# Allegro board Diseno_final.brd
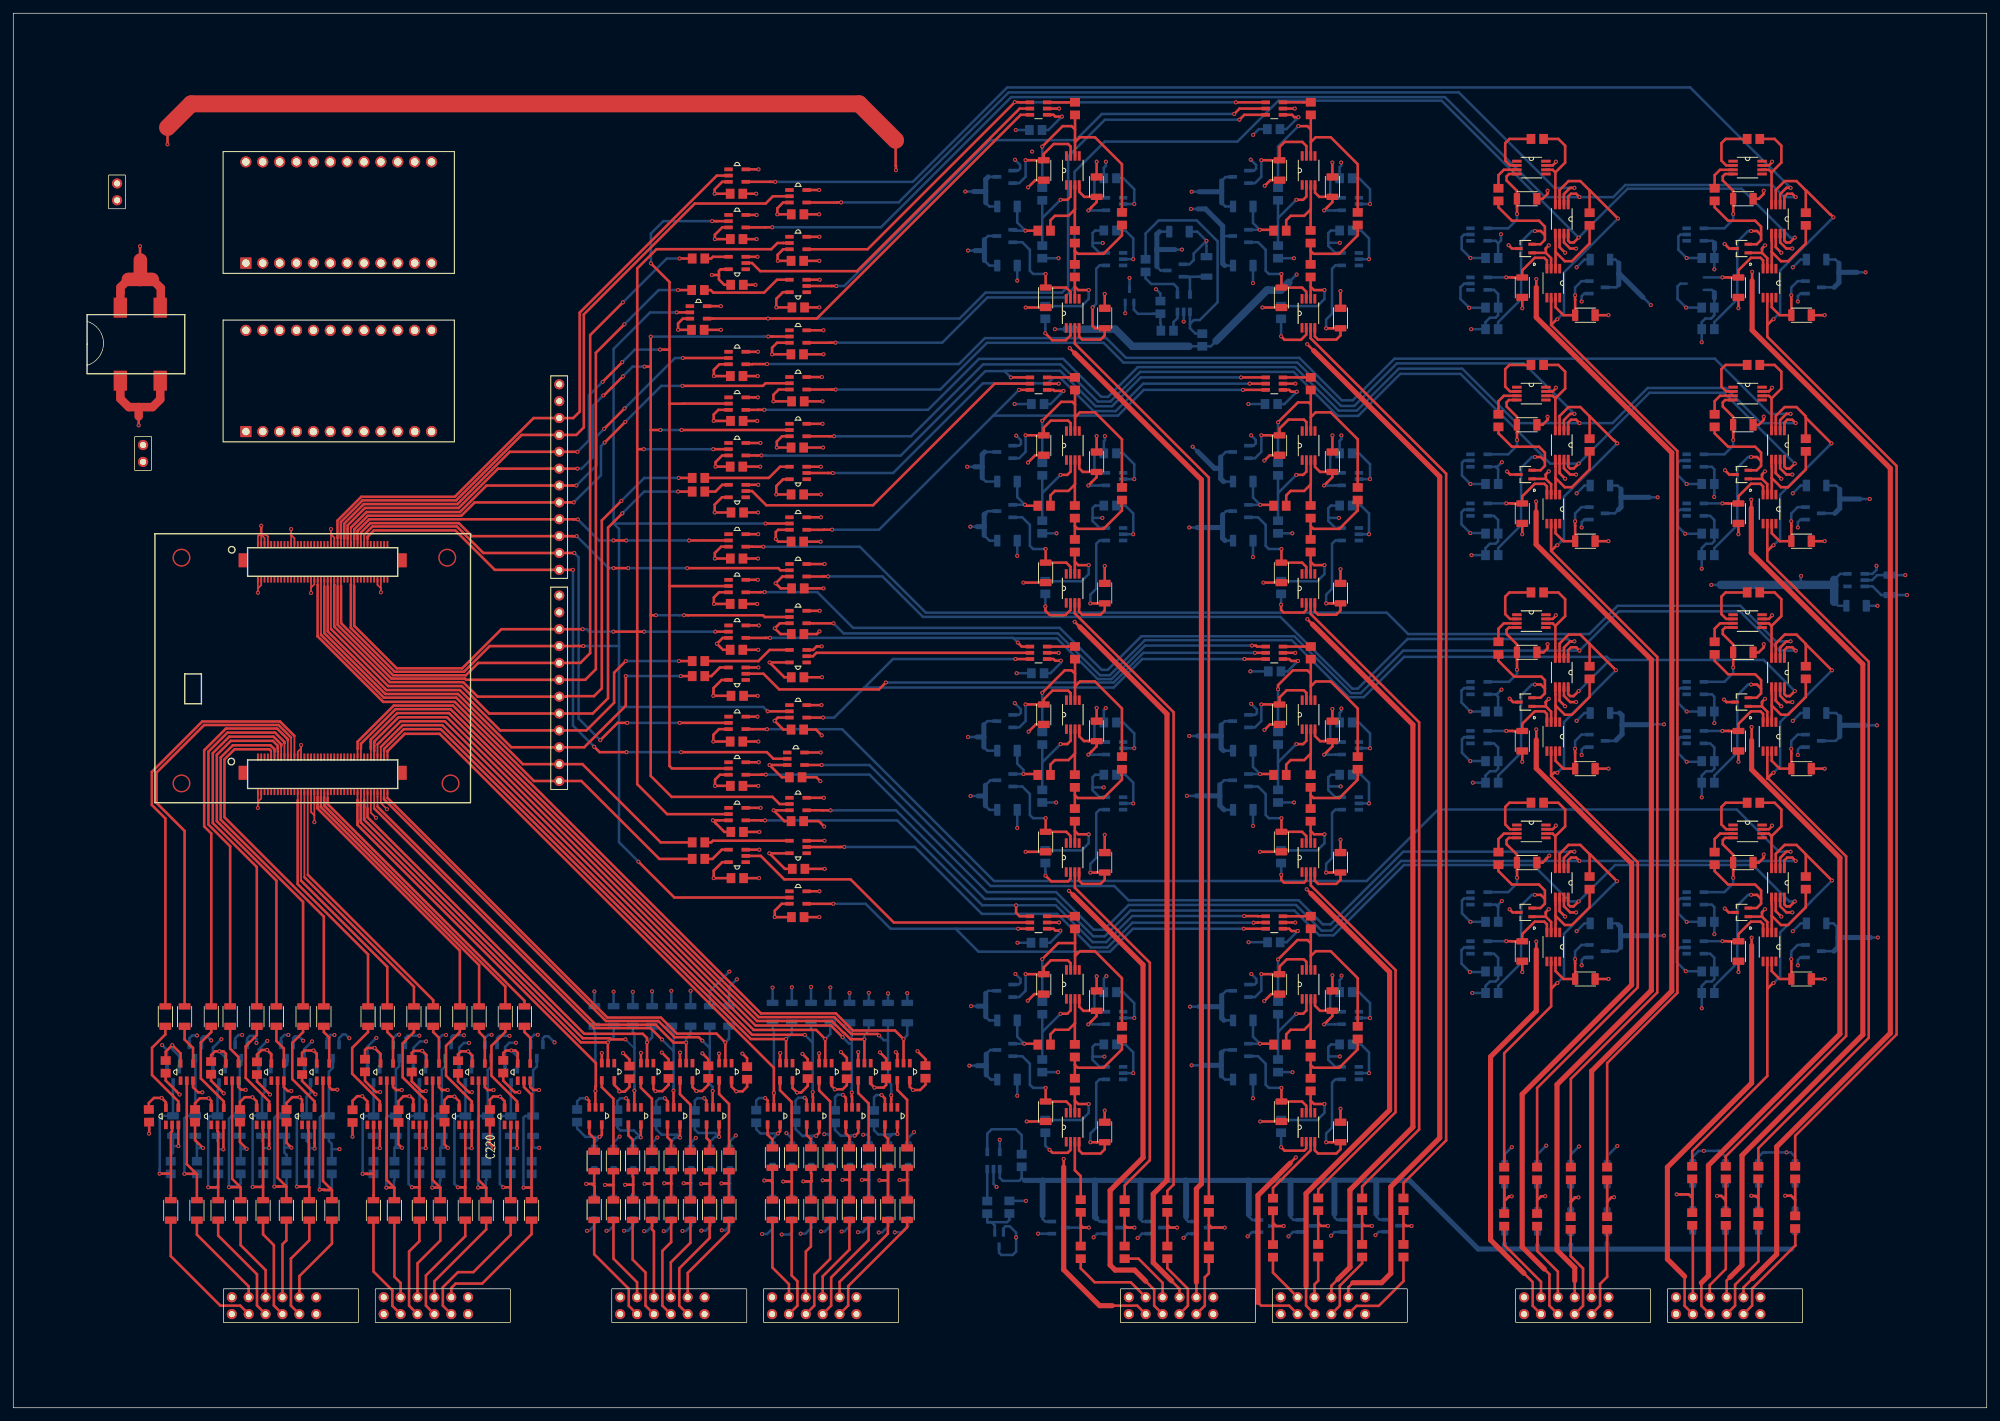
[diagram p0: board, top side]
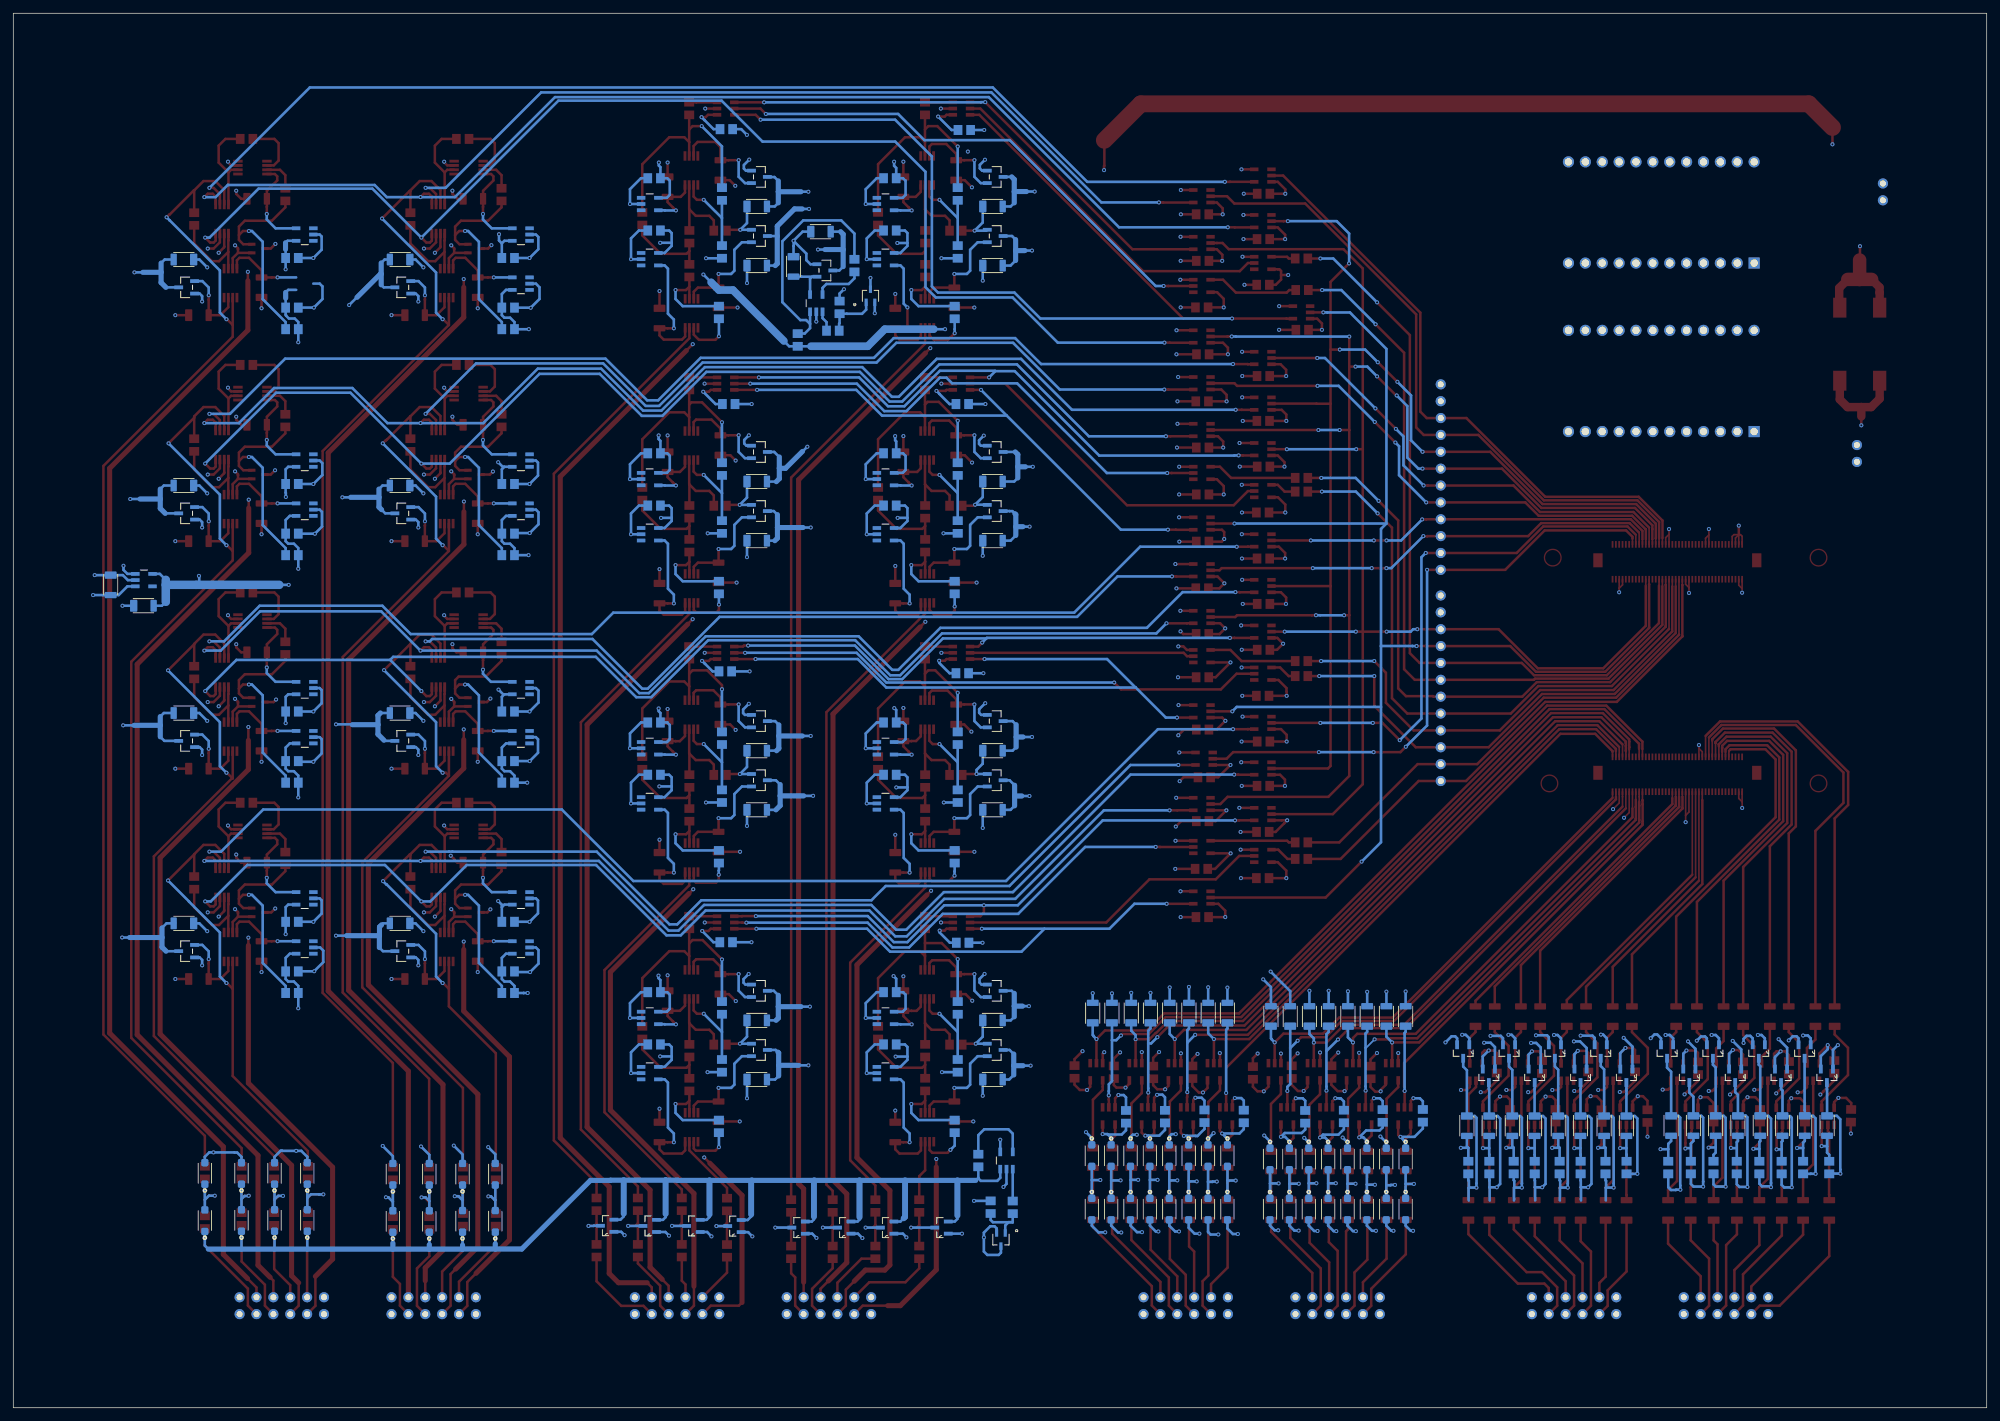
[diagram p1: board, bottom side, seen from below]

Outline 297 x 210.01 mm; copper layers: TOP, GND, VCC, BOTTOM. Coordinates in mm from the lower left corner of the outline.
Outline path: rectangle 0,0 297,210.01

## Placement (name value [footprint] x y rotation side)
C1  1uF  [1206]  175.51 177.11 180 bottom
C2  1uF  [1206]  179.58 171.88 270 bottom
C4  1uF  [1206]  149.63 49.43 180 bottom
C5  1uF  [1206]  155.37 44.58 90 top
C7  1uF  [1206]  155.09 63.75 90 top
C8  1uF  [1206]  149.63 58.34 180 bottom
C9  0.1uF  [0805]  166.85 56.49 90 top
C10  82pF  [0805]  155.14 54.69 0 top
C11  1uF  [0805]  165.07 54.71 180 bottom
C12  1uF  [1206]  164.26 41.53 270 top
C13  1uF  [0805]  165.07 62.59 180 bottom
C14  1uF  [1206]  163.04 61.32 270 top
C15  1uF  [1206]  149.63 90.04 180 bottom
C16  1uF  [1206]  155.37 85.19 90 top
C17  1uF  [1206]  155.09 104.37 90 top
C18  1uF  [1206]  149.63 98.95 180 bottom
C19  0.1uF  [0805]  166.85 97.1 90 top
C20  82pF  [0805]  155.14 95.3 0 top
C21  1uF  [1206]  164.26 82.14 270 top
C22  1uF  [0805]  165.07 95.33 180 bottom
C23  1uF  [0805]  165.07 103.2 180 bottom
C24  1uF  [1206]  163.04 101.93 270 top
C25  1uF  [1206]  149.63 130.58 180 bottom
C26  1uF  [1206]  155.37 125.73 90 top
C27  1uF  [1206]  155.09 144.91 90 top
C28  1uF  [1206]  149.63 139.49 180 bottom
C29  0.1uF  [0805]  166.85 137.64 90 top
C30  82pF  [0805]  155.14 135.84 0 top
C31  1uF  [1206]  164.26 122.68 270 top
C32  1uF  [0805]  165.07 135.86 180 bottom
C33  1uF  [0805]  165.07 143.74 180 bottom
C34  1uF  [1206]  163.04 142.47 270 top
C35  1uF  [1206]  149.63 172.01 180 bottom
C36  1uF  [1206]  155.37 167.16 90 top
C37  1uF  [1206]  155.09 186.33 90 top
C38  1uF  [1206]  149.63 180.92 180 bottom
C39  0.1uF  [0805]  166.85 179.07 90 top
C40  82pF  [0805]  155.14 177.27 0 top
C41  1uF  [1206]  164.26 164.11 270 top
C42  1uF  [0805]  165.07 177.29 180 bottom
C43  1uF  [0805]  165.07 185.17 180 bottom
C44  1uF  [1206]  163.04 183.9 270 top
C45  1uF  [1206]  185.12 49.43 180 bottom
C46  1uF  [1206]  190.86 44.58 90 top
C47  1uF  [1206]  190.58 63.75 90 top
C48  1uF  [1206]  185.12 58.34 180 bottom
C49  0.1uF  [0805]  202.34 56.49 90 top
C50  82pF  [0805]  190.63 54.69 0 top
C51  1uF  [1206]  199.75 41.53 270 top
C52  1uF  [0805]  200.56 54.71 180 bottom
C53  1uF  [0805]  200.56 62.59 180 bottom
C54  1uF  [1206]  198.53 61.32 270 top
C55  1uF  [1206]  185.12 90.04 180 bottom
C56  1uF  [1206]  190.86 85.19 90 top
C57  1uF  [1206]  190.58 104.37 90 top
C58  1uF  [1206]  185.12 98.95 180 bottom
C59  0.1uF  [0805]  202.34 97.1 90 top
C60  82pF  [0805]  190.63 95.3 0 top
C61  1uF  [1206]  199.75 82.14 270 top
C62  1uF  [0805]  200.56 95.33 180 bottom
C63  1uF  [0805]  200.56 103.2 180 bottom
C64  1uF  [1206]  198.53 101.93 270 top
C65  1uF  [1206]  185.12 130.58 180 bottom
C66  1uF  [1206]  190.86 125.73 90 top
C67  1uF  [1206]  190.58 144.91 90 top
C68  1uF  [1206]  185.12 139.49 180 bottom
C69  0.1uF  [0805]  202.34 137.64 90 top
C70  82pF  [0805]  190.63 135.84 0 top
C71  1uF  [1206]  199.75 122.68 270 top
C72  1uF  [0805]  200.56 135.86 180 bottom
C73  1uF  [0805]  200.56 143.74 180 bottom
C74  1uF  [1206]  198.53 142.47 270 top
C75  1uF  [1206]  185.12 172.01 180 bottom
C76  1uF  [1206]  190.86 167.16 90 top
C77  1uF  [1206]  190.58 186.33 90 top
C78  1uF  [1206]  185.12 180.92 180 bottom
C79  0.1uF  [0805]  202.34 179.07 90 top
C80  82pF  [0805]  190.63 177.27 0 top
C81  1uF  [1206]  199.75 164.11 270 top
C82  1uF  [0805]  200.56 177.29 180 bottom
C83  1uF  [0805]  200.56 185.17 180 bottom
C84  1uF  [1206]  198.53 183.9 270 top
C85  1uF  [1206]  282.35 123.93 270 bottom
C86  2.2uF  [1206]  277.42 120.78 180 bottom
C87  1uF  [1206]  236.6 64.57 180 top
C88  1uF  [1206]  238.79 72.95 0 bottom
C89  15pF  [0805]  237.24 79.04 270 top
C90  1uF  [0805]  222.52 73.18 0 bottom
C91  1uF  [1206]  227.84 82.09 180 top
C92  1uF  [0805]  222.52 65.7 0 bottom
C93  1uF  [1206]  227.1 68.71 90 top
C96  1uF  [1206]  238.79 104.62 0 bottom
C97  1uF  [1206]  236.6 96.24 180 top
C98  15pF  [0805]  237.24 110.72 270 top
C99  1uF  [0805]  222.52 104.85 0 bottom
C100  1uF  [1206]  227.84 113.77 180 top
C101  1uF  [0805]  222.52 97.38 0 bottom
C102  1uF  [1206]  227.1 100.38 90 top
C105  1uF  [1206]  238.79 138.89 0 bottom
C106  1uF  [1206]  236.6 130.51 180 top
C107  15pF  [0805]  237.24 144.98 270 top
C108  1uF  [0805]  222.52 139.12 0 bottom
C109  1uF  [1206]  227.84 148.03 180 top
C110  1uF  [0805]  222.52 131.64 0 bottom
C111  1uF  [1206]  227.1 134.65 90 top
C114  1uF  [1206]  238.79 172.92 0 bottom
C115  1uF  [1206]  236.6 164.54 180 top
C116  15pF  [0805]  237.24 179.02 270 top
C117  1uF  [0805]  222.52 173.15 0 bottom
C118  1uF  [1206]  227.84 182.07 180 top
C119  1uF  [0805]  222.52 165.68 0 bottom
C120  1uF  [1206]  227.1 168.68 90 top
C123  1uF  [1206]  271.32 72.95 0 bottom
C124  1uF  [1206]  269.14 64.57 180 top
C125  15pF  [0805]  269.77 79.04 270 top
C126  1uF  [0805]  255.06 73.18 0 bottom
C127  1uF  [1206]  260.38 82.09 180 top
C128  1uF  [0805]  255.06 65.7 0 bottom
C129  1uF  [1206]  259.64 68.71 90 top
C132  1uF  [1206]  271.32 104.62 0 bottom
C133  1uF  [1206]  269.14 96.24 180 top
C134  15pF  [0805]  269.77 110.72 270 top
C135  1uF  [0805]  255.06 104.85 0 bottom
C136  1uF  [1206]  260.38 113.77 180 top
C137  1uF  [0805]  255.06 97.38 0 bottom
C138  1uF  [1206]  259.64 100.38 90 top
C141  1uF  [1206]  271.32 138.89 0 bottom
C142  1uF  [1206]  269.14 130.51 180 top
C143  15pF  [0805]  269.77 144.98 270 top
C144  1uF  [0805]  255.06 139.12 0 bottom
C145  1uF  [1206]  260.38 148.03 180 top
C146  1uF  [0805]  255.06 131.64 0 bottom
C147  1uF  [1206]  259.64 134.65 90 top
C150  1uF  [1206]  271.32 172.92 0 bottom
C151  1uF  [1206]  269.14 164.54 180 top
C152  15pF  [0805]  269.77 179.02 270 top
C153  1uF  [0805]  255.06 173.15 0 bottom
C154  1uF  [1206]  260.38 182.07 180 top
C155  1uF  [0805]  255.06 165.68 0 bottom
C156  1uF  [1206]  259.64 168.68 90 top
C157  5p6  [0805]  23.7 36.17 90 bottom
C158  5p6  [0805]  30.86 36.17 90 bottom
C159  5p6  [0805]  37.62 36.17 90 bottom
C160  5p6  [0805]  44.53 36.17 90 bottom
C161  5p6  [0805]  27.64 36.17 90 bottom
C162  5p6  [0805]  34.21 36.17 90 bottom
C163  5p6  [0805]  41.12 36.17 90 bottom
C164  5p6  [0805]  47.93 36.17 90 bottom
C165  5p6  [0805]  54.2 36.17 90 bottom
C166  5p6  [0805]  61.11 36.17 90 bottom
C167  5p6  [0805]  68.02 36.17 90 bottom
C168  5p6  [0805]  74.85 36.17 90 bottom
C169  5p6  [0805]  57.37 36.17 90 bottom
C170  5p6  [0805]  64.28 36.17 90 bottom
C171  5p6  [0805]  71.19 36.17 90 bottom
C172  5p6  [0805]  78.02 36.17 90 bottom
C173  0.1uF  [0805]  154.13 70.03 0 bottom
C174  0.1uF  [0805]  154.18 110.62 0 bottom
C175  0.1uF  [0805]  154.18 151.16 0 bottom
C176  0.1uF  [0805]  153.87 192.43 0 bottom
C177  0.1uF  [0805]  189.71 70.1 0 bottom
C178  0.1uF  [0805]  189.84 110.9 0 bottom
C179  0.1uF  [0805]  189.33 151.16 0 bottom
C180  0.1uF  [0805]  189.69 192.56 0 bottom
C181  0.1uF  [0805]  108.97 79.76 0 top
C182  0.1uF  [0805]  118.06 73.89 180 top
C183  0.1uF  [0805]  108.94 86.72 180 top
C184  0.1uF  [0805]  118.03 110.01 0 top
C185  0.1uF  [0805]  118.01 102.13 180 top
C186  0.1uF  [0805]  108.84 114.15 180 top
C187  0.1uF  [0805]  108.97 134.82 0 top
C188  0.1uF  [0805]  118.01 130.43 180 top
C189  0.1uF  [0805]  108.84 141.73 180 top
C190  0.1uF  [0805]  108.92 169.11 0 top
C191  0.1uF  [0805]  103.02 162.33 180 top
C192  0.1uF  [0805]  118.01 172.72 180 top
C193  0.1uF  [0805]  118.19 81.15 0 top
C194  0.1uF  [0805]  108.97 107.21 0 top
C195  0.1uF  [0805]  118.01 137.54 0 top
C196  0.1uF  [0805]  118.14 165.71 0 top
C197  0.1uF  [0805]  118.03 116.51 180 top
C198  0.1uF  [0805]  108.84 121.06 180 top
C199  0.1uF  [0805]  118.08 151.56 180 top
C200  0.1uF  [0805]  118.01 144.6 180 top
C201  0.1uF  [0805]  108.89 148.62 180 top
C202  0.1uF  [0805]  118.03 179.73 180 top
C203  0.1uF  [0805]  108.86 176 180 top
C204  0.1uF  [0805]  117.98 158.65 180 top
C205  0.1uF  [0805]  108.84 100.33 180 top
C206  0.1uF  [0805]  108.86 127.89 180 top
C207  0.1uF  [0805]  108.86 155.37 180 top
C208  0.1uF  [0805]  108.84 182.83 180 top
C209  0.1uF  [0805]  20.42 43.97 271 top
C210  0.1uF  [0805]  27.36 43.97 270 top
C211  0.1uF  [0805]  34.11 43.97 270 top
C212  0.1uF  [0805]  41.12 43.97 270 top
C213  0.1uF  [0805]  22.94 51.33 270 top
C214  0.1uF  [0805]  29.77 51.18 270 top
C215  0.1uF  [0805]  36.68 51.13 270 top
C216  0.1uF  [0805]  43.46 51.13 270 top
C217  0.1uF  [0805]  51.05 43.92 270 top
C218  0.1uF  [0805]  57.96 43.92 270 top
C219  0.1uF  [0805]  64.9 43.97 270 top
C220  0.1uF  [0805]  71.73 43.97 270 top
C221  0.1uF  [0805]  52.93 51.54 270 top
C222  0.1uF  [0805]  59.97 51.51 270 top
C223  0.1uF  [0805]  66.93 51.31 270 top
C224  0.1uF  [0805]  73.74 51.36 270 top
C225  0.1uF  [0805]  84.86 43.97 90 bottom
C226  0.1uF  [0805]  90.91 43.94 90 bottom
C227  0.1uF  [0805]  96.75 43.87 90 bottom
C228  0.1uF  [0805]  102.57 43.81 90 bottom
C229  0.1uF  [0805]  98.63 50.55 90 top
C230  0.1uF  [0805]  104.6 50.55 90 top
C231  0.1uF  [0805]  110.44 50.42 90 top
C232  0.1uF  [0805]  92.74 50.5 90 top
C233  0.1uF  [0805]  111.81 43.87 90 bottom
C234  0.1uF  [0805]  117.73 43.89 90 bottom
C235  0.1uF  [0805]  123.67 43.84 90 bottom
C236  0.1uF  [0805]  129.54 43.81 90 bottom
C237  0.1uF  [0805]  119.56 50.52 90 top
C238  0.1uF  [0805]  125.45 50.5 90 top
C239  0.1uF  [0805]  131.37 50.52 90 top
C240  0.1uF  [0805]  137.29 50.57 90 top
C241  0.1uF  [0805]  118.01 88.34 180 top
C242  0.1uF  [0805]  108.86 93.65 180 top
C243  0.1uF  [0805]  117.75 94.95 180 top
C244  0.1uF  [0805]  118.08 123.39 180 top
D17  0.3V  [SOD123]  224.46 28.09 90 bottom
D18  0.3V  [SOD123]  224.46 35.18 90 bottom
D19  0.3V  [SOD123]  229.39 28.09 90 bottom
D20  0.3V  [SOD123]  229.39 35.18 90 bottom
D21  0.3V  [SOD123]  234.39 28.07 90 bottom
D22  0.3V  [SOD123]  234.39 35.18 90 bottom
D23  0.3V  [SOD123]  239.88 28.07 90 bottom
D24  0.3V  [SOD123]  239.88 35.18 90 bottom
D25  0.3V  [SOD123]  252.76 28.22 90 bottom
D26  0.3V  [SOD123]  252.76 35.31 90 bottom
D27  0.3V  [SOD123]  257.68 28.22 90 bottom
D28  0.3V  [SOD123]  257.68 35.31 90 bottom
D29  0.3V  [SOD123]  262.66 28.22 90 bottom
D30  0.3V  [SOD123]  262.66 35.31 90 bottom
D31  0.3V  [SOD123]  268.17 28.19 90 bottom
D32  0.3V  [SOD123]  268.17 35.31 90 bottom
D65  0.3V  [SOD123]  87.45 37.44 270 bottom
D66  0.3V  [SOD123]  87.45 29.9 270 bottom
D67  0.3V  [SOD123]  93.28 37.44 270 bottom
D68  0.3V  [SOD123]  93.28 29.9 270 bottom
D69  0.3V  [SOD123]  99.12 37.44 270 bottom
D70  0.3V  [SOD123]  99.12 29.9 270 bottom
D71  0.3V  [SOD123]  104.95 37.44 270 bottom
D72  0.3V  [SOD123]  104.95 29.9 270 bottom
D73  0.3V  [SOD123]  90.37 37.44 270 bottom
D74  0.3V  [SOD123]  90.37 29.9 270 bottom
D75  0.3V  [SOD123]  96.2 37.44 270 bottom
D76  0.3V  [SOD123]  96.2 29.9 270 bottom
D77  0.3V  [SOD123]  102.03 37.44 270 bottom
D78  0.3V  [SOD123]  102.03 29.9 270 bottom
D79  0.3V  [SOD123]  107.86 37.44 270 bottom
D80  0.3V  [SOD123]  107.86 29.9 270 bottom
D81  0.3V  [SOD123]  114.27 37.95 270 bottom
D82  0.3V  [SOD123]  114.27 29.9 270 bottom
D83  0.3V  [SOD123]  120.11 37.95 270 bottom
D84  0.3V  [SOD123]  120.11 29.9 270 bottom
D85  0.3V  [SOD123]  125.94 37.95 270 bottom
D86  0.3V  [SOD123]  125.94 29.9 270 bottom
D87  0.3V  [SOD123]  131.77 37.95 270 bottom
D88  0.3V  [SOD123]  131.77 29.9 270 bottom
D89  0.3V  [SOD123]  117.19 37.95 270 bottom
D90  0.3V  [SOD123]  117.19 29.9 270 bottom
D91  0.3V  [SOD123]  123.02 37.95 270 bottom
D92  0.3V  [SOD123]  123.02 29.9 270 bottom
D93  0.3V  [SOD123]  128.85 37.95 270 bottom
D94  0.3V  [SOD123]  128.85 29.9 270 bottom
D95  0.3V  [SOD123]  134.69 37.95 270 bottom
D96  0.3V  [SOD123]  134.69 29.9 270 bottom
J1  CON12  [JUMPER12]  32.89 14.1 0 top
J3  CON12  [JUMPER12_F]  167.89 14.1 0 top
J5  CON12  [JUMPER12]  55.75 14.1 0 top
J7  CON12  [JUMPER12_F]  190.75 14.1 0 top
J9  CON12  [JUMPER12]  91.34 14.1 0 top
J10  CON12  [JUMPER12_F]  227.38 14.1 0 top
J13  CON12  [JUMPER12]  114.2 14.1 0 top
J14  CON12  [JUMPER12_F]  250.24 14.1 0 top
J15  CON12  [JUMPER12X1]  82.17 94.39 90 top
J16  CON12  [JUMPER12X1]  82.17 126.19 90 top
J17  CON2  [JUMPER2]  19.53 142.44 90 top
J18  CON2  [JUMPER2]  15.62 181.84 90 top
R1  6k8  [0805]  172.64 165.71 270 bottom
R2  953  [0805]  173.66 162.2 0 bottom
R3  953  [0805]  170.41 172.01 90 bottom
R4  200  [0805]  103.12 82.65 180 top
R5  8k45  [0805]  160.66 30.38 90 top
R6  51  [0805]  159.79 73.08 270 top
R7  1k5  [0805]  159.77 48.67 270 top
R8  1k5  [0805]  159.77 53.77 270 top
R9  845  [0805]  160.66 23.39 90 top
R10  3k3  [0805]  154.86 60.21 270 bottom
R11  10k5  [0805]  155.32 42.37 270 bottom
R12  33k  [0805]  154.86 51.49 270 bottom
R13  200  [0805]  103.12 112.45 180 top
R14  51  [0805]  159.79 113.69 270 top
R15  1k5  [0805]  159.77 89.28 270 top
R16  1k5  [0805]  159.77 94.39 270 top
R17  845  [0805]  167.26 23.39 90 top
R18  8k45  [0805]  167.26 30.38 90 top
R19  3k3  [0805]  154.86 100.83 270 bottom
R20  10k5  [0805]  155.32 82.98 270 bottom
R21  33k  [0805]  154.86 92.1 270 bottom
R22  200  [0805]  103.12 137.97 180 top
R23  845  [0805]  173.69 23.39 90 top
R24  51  [0805]  159.79 154.23 270 top
R25  1k5  [0805]  159.77 129.82 270 top
R26  1k5  [0805]  159.77 134.92 270 top
R27  8k45  [0805]  173.69 30.38 90 top
R28  3k3  [0805]  154.86 141.36 270 bottom
R29  10k5  [0805]  155.32 123.52 270 bottom
R30  33k  [0805]  154.86 132.64 270 bottom
R31  200  [0805]  103.12 173.08 180 top
R32  51  [0805]  159.79 195.66 270 top
R33  1k5  [0805]  159.77 171.25 270 top
R34  1k5  [0805]  159.77 176.35 270 top
R35  845  [0805]  179.93 23.39 90 top
R36  8k45  [0805]  179.93 30.38 90 top
R37  3k3  [0805]  154.86 182.79 270 bottom
R38  10k5  [0805]  155.32 164.95 270 bottom
R39  33k  [0805]  154.86 174.07 270 bottom
R40  200  [0805]  103.12 85.14 180 top
R41  1k5  [0805]  195.25 53.77 270 top
R42  845  [0805]  189.59 23.62 90 top
R43  8k45  [0805]  189.59 30.61 90 top
R44  51  [0805]  195.28 73.08 270 top
R45  1k5  [0805]  195.25 48.67 270 top
R46  3k3  [0805]  190.35 60.21 270 bottom
R47  10k5  [0805]  190.8 42.37 270 bottom
R48  33k  [0805]  190.35 51.49 270 bottom
R49  200  [0805]  103.12 110.19 180 top
R50  1k5  [0805]  195.25 89.28 270 top
R51  1k5  [0805]  195.25 94.39 270 top
R52  845  [0805]  196.39 23.65 90 top
R53  51  [0805]  195.28 113.69 270 top
R54  8k45  [0805]  196.39 30.63 90 top
R55  3k3  [0805]  190.35 100.83 270 bottom
R56  10k5  [0805]  190.8 82.98 270 bottom
R57  33k  [0805]  190.35 92.1 270 bottom
R58  200  [0805]  103.12 140.03 180 top
R59  845  [0805]  203 23.65 90 top
R60  51  [0805]  195.28 154.23 270 top
R61  1k5  [0805]  195.25 129.82 270 top
R62  1k5  [0805]  195.25 134.92 270 top
R63  8k45  [0805]  203 30.63 90 top
R64  3k3  [0805]  190.35 141.36 270 bottom
R65  10k5  [0805]  190.8 123.52 270 bottom
R66  33k  [0805]  190.35 132.64 270 bottom
R67  200  [0805]  103.05 168.33 180 top
R68  51  [0805]  195.28 195.66 270 top
R69  1k5  [0805]  195.25 171.25 270 top
R70  1k5  [0805]  195.25 176.35 270 top
R71  845  [0805]  209.22 23.65 90 top
R72  8k45  [0805]  209.22 30.63 90 top
R73  3k3  [0805]  190.35 182.79 270 bottom
R74  10k5  [0805]  190.8 164.95 270 bottom
R75  33k  [0805]  190.35 174.07 270 bottom
R76  953  [0805]  151.76 37.23 90 bottom
R77  6k8  [0805]  149.91 30.2 90 bottom
R78  953  [0805]  146.58 30.18 270 bottom
R79  953  [0805]  229.36 91.11 180 top
R80  6k8  [0805]  222.52 62.46 180 bottom
R81  953  [0805]  223.52 82.73 270 top
R82  360  [0805]  224.38 35.28 270 top
R83  845  [0805]  224.38 28.3 270 top
R84  953  [0805]  229.36 122.78 180 top
R85  6k8  [0805]  222.52 94.13 180 bottom
R86  360  [0805]  229.34 35.28 270 top
R87  845  [0805]  229.34 28.3 270 top
R88  953  [0805]  223.52 114.4 270 top
R89  953  [0805]  229.36 157.05 180 top
R90  6k8  [0805]  222.52 128.4 180 bottom
R91  953  [0805]  223.52 148.67 270 top
R92  360  [0805]  234.42 35.28 270 top
R93  845  [0805]  234.39 27.81 270 top
R94  953  [0805]  229.36 191.08 180 top
R95  6k8  [0805]  222.52 162.43 180 bottom
R96  360  [0805]  239.88 35.28 270 top
R97  845  [0805]  239.88 27.81 270 top
R98  953  [0805]  223.52 182.7 270 top
R99  953  [0805]  261.9 91.11 180 top
R100  6k8  [0805]  255.06 62.46 180 bottom
R101  360  [0805]  252.68 35.41 270 top
R102  845  [0805]  252.68 28.42 270 top
R103  953  [0805]  256.06 82.73 270 top
R104  953  [0805]  261.9 122.78 180 top
R105  6k8  [0805]  255.06 94.13 180 bottom
R106  360  [0805]  257.73 35.41 270 top
R107  845  [0805]  257.73 28.42 270 top
R108  953  [0805]  256.06 114.4 270 top
R109  953  [0805]  261.9 157.05 180 top
R110  6k8  [0805]  255.06 128.4 180 bottom
R111  360  [0805]  262.64 35.41 270 top
R112  845  [0805]  262.64 28.42 270 top
R113  953  [0805]  256.06 148.67 270 top
R114  953  [0805]  261.9 191.08 180 top
R115  6k8  [0805]  255.06 162.43 180 bottom
R116  360  [0805]  268.17 35.41 270 top
R117  845  [0805]  268.17 27.94 270 top
R118  953  [0805]  256.06 182.7 270 top
R119  1k  [1206]  23.7 29.72 90 top
R120  200  [1206]  22.89 58.9 90 top
R121  20k  [1206]  24.03 42.49 270 bottom
R122  1k  [1206]  30.84 29.72 90 top
R123  200  [1206]  29.79 58.9 90 top
R124  20k  [1206]  30.73 42.49 270 bottom
R125  1k  [1206]  37.59 29.72 90 top
R126  200  [1206]  36.65 58.9 90 top
R127  20k  [1206]  37.44 42.49 270 bottom
R128  1k  [1206]  44.55 29.72 90 top
R129  200  [1206]  43.61 58.9 90 top
R130  20k  [1206]  44.15 42.49 270 bottom
R131  200  [1206]  25.78 58.9 90 top
R132  1k  [1206]  27.64 29.72 90 top
R133  20k  [1206]  27.38 42.49 270 bottom
R134  200  [1206]  32.64 58.9 90 top
R135  1k  [1206]  34.21 29.72 90 top
R136  20k  [1206]  34.09 42.49 270 bottom
R137  200  [1206]  39.6 58.9 90 top
R138  1k  [1206]  41.1 29.72 90 top
R139  20k  [1206]  40.79 42.49 270 bottom
R140  1k  [1206]  47.96 29.72 90 top
R141  200  [1206]  46.74 58.9 90 top
R142  20k  [1206]  47.5 42.49 270 bottom
R143  1k  [1206]  54.2 29.72 90 top
R144  200  [1206]  53.39 58.9 90 top
R145  20k  [1206]  54.23 42.47 270 bottom
R146  1k  [1206]  61.11 29.72 90 top
R147  200  [1206]  60.3 58.9 90 top
R148  20k  [1206]  61.14 42.47 270 bottom
R149  1k  [1206]  68.02 29.72 90 top
R150  200  [1206]  67.21 58.9 90 top
R151  20k  [1206]  68.05 42.47 270 bottom
R152  1k  [1206]  74.85 29.72 90 top
R153  200  [1206]  74.04 58.9 90 top
R154  20k  [1206]  74.88 42.47 270 bottom
R155  1k  [1206]  57.35 29.72 90 top
R156  200  [1206]  56.29 58.9 90 top
R157  20k  [1206]  57.58 42.47 270 bottom
R158  1k  [1206]  64.26 29.72 90 top
R159  200  [1206]  63.2 58.9 90 top
R160  20k  [1206]  64.49 42.47 270 bottom
R161  1k  [1206]  71.17 29.72 90 top
R162  200  [1206]  70.1 58.9 90 top
R163  20k  [1206]  71.4 42.47 270 bottom
R164  1k  [1206]  78 29.72 90 top
R165  200  [1206]  76.94 58.9 90 top
R166  20k  [1206]  78.23 42.47 270 bottom
R167  10k  [1206]  87.45 58.93 90 bottom
R168  300  [1206]  87.43 37.16 270 top
R169  604  [1206]  87.43 29.82 270 top
R170  10k  [1206]  93.24 58.93 90 bottom
R171  300  [1206]  93.22 37.16 270 top
R172  604  [1206]  93.22 29.82 270 top
R173  10k  [1206]  99.03 58.93 90 bottom
R174  300  [1206]  99.01 37.16 270 top
R175  604  [1206]  99.01 29.82 270 top
R176  10k  [1206]  104.83 58.93 90 bottom
R177  300  [1206]  104.8 37.16 270 top
R178  604  [1206]  104.8 29.82 270 top
R179  10k  [1206]  90.35 58.93 90 bottom
R180  300  [1206]  90.32 37.16 270 top
R181  604  [1206]  90.32 29.82 270 top
R182  10k  [1206]  96.14 58.93 90 bottom
R183  300  [1206]  96.11 37.16 270 top
R184  604  [1206]  96.11 29.82 270 top
R185  10k  [1206]  101.93 58.93 90 bottom
R186  300  [1206]  101.9 37.16 270 top
R187  604  [1206]  101.9 29.82 270 top
R188  10k  [1206]  107.72 58.93 90 bottom
R189  300  [1206]  107.7 37.16 270 top
R190  604  [1206]  107.7 29.82 270 top
R191  10k  [1206]  114.27 59.44 90 bottom
R192  300  [1206]  114.25 37.67 270 top
R193  604  [1206]  114.25 29.82 270 top
R194  10k  [1206]  120.07 59.44 90 bottom
R195  300  [1206]  120.04 37.67 270 top
R196  604  [1206]  120.04 29.82 270 top
R197  10k  [1206]  125.86 59.44 90 bottom
R198  300  [1206]  125.83 37.67 270 top
R199  604  [1206]  125.83 29.82 270 top
R200  10k  [1206]  131.65 59.44 90 bottom
R201  300  [1206]  131.62 37.67 270 top
R202  604  [1206]  131.62 29.82 270 top
R203  10k  [1206]  117.17 59.44 90 bottom
R204  300  [1206]  117.14 37.67 270 top
R205  604  [1206]  117.14 29.82 270 top
R206  10k  [1206]  122.96 59.44 90 bottom
R207  300  [1206]  122.94 37.67 270 top
R208  604  [1206]  122.94 29.82 270 top
R209  10k  [1206]  128.75 59.44 90 bottom
R210  300  [1206]  128.73 37.67 270 top
R211  604  [1206]  128.73 29.82 270 top
R212  10k  [1206]  134.54 59.44 90 bottom
R213  300  [1206]  134.52 37.67 270 top
R214  604  [1206]  134.52 29.82 270 top
R223  10  [0805]  178.94 160.81 270 bottom
U1  MCP1702T-4002ECB  [SOT23A]  174.85 171.27 270 bottom
U2  MCP1702T-4002ECB  [SOT23A]  149.23 53.88 270 bottom
U3  OPA365AMDBVTEP  [SOT_23_5]  176.15 166.34 90 bottom
U4  LM4040AEX3-3_3T  [SC_70_3]  168 167.46 180 bottom
U5  MCP1702T-4002ECB  [SOT23A]  149.23 62.79 270 bottom
U6  AD7476AAKSZ-REEL7  [SOT95P280X145-6N]  154.31 73.08 180 top
U7  OPA727AIDGKT  [SOP65P490X110-8N]  159.44 42.24 90 top
U8  OPA727AIDGKT  [SOP65P490X110-8N]  159.46 63.75 90 top
U9  MIC5270-4.1YM5-TR  [SOT95P280X145-5N]  165.74 50.39 180 bottom
U10  MIC5270-4.1YM5-TR  [SOT95P280X145-5N]  165.74 58.7 180 bottom
U11  MCP1702T-4002ECB  [SOT23A]  149.23 94.5 270 bottom
U12  MCP1702T-4002ECB  [SOT23A]  149.23 103.4 270 bottom
U13  AD7476AAKSZ-500RL7  [SOT95P280X145-6N]  154.31 113.69 180 top
U14  OPA727AIDGKT  [SOP65P490X110-8N]  159.44 82.85 90 top
U15  OPA727AIDGKT  [SOP65P490X110-8N]  159.46 104.37 90 top
U16  MIC5270-4.1YM5-TR  [SOT95P280X145-5N]  165.74 91.01 180 bottom
U17  MIC5270-4.1YM5-TR  [SOT95P280X145-5N]  165.74 99.31 180 bottom
U18  MCP1702T-4002ECB  [SOT23A]  149.23 135.03 270 bottom
U19  MCP1702T-4002ECB  [SOT23A]  149.23 143.94 270 bottom
U20  AD7476AAKSZ-500RL7  [SOT95P280X145-6N]  154.31 154.23 180 top
U21  OPA727AIDGKT  [SOP65P490X110-8N]  159.44 123.39 90 top
U22  OPA727AIDGKT  [SOP65P490X110-8N]  159.46 144.91 90 top
U23  MIC5270-4.1YM5-TR  [SOT95P280X145-5N]  165.74 131.55 180 bottom
U24  MIC5270-4.1YM5-TR  [SOT95P280X145-5N]  165.74 139.85 180 bottom
U25  MCP1702T-4002ECB  [SOT23A]  149.23 176.46 270 bottom
U26  MCP1702T-4002ECB  [SOT23A]  149.23 185.37 270 bottom
U27  AD7476AAKSZ-500RL7  [SOT95P280X145-6N]  154.31 195.66 180 top
U28  OPA727AIDGKT  [SOP65P490X110-8N]  159.46 186.33 90 top
U29  OPA727AIDGKT  [SOP65P490X110-8N]  159.44 164.82 90 top
U30  MIC5270-4.1YM5-TR  [SOT95P280X145-5N]  165.74 172.97 180 bottom
U31  MIC5270-4.1YM5-TR  [SOT95P280X145-5N]  165.74 181.28 180 bottom
U32  MCP1702T-4002ECB  [SOT23A]  184.71 53.88 270 bottom
U33  MCP1702T-4002ECB  [SOT23A]  184.71 62.79 270 bottom
U34  AD7476AAKSZ-500RL7  [SOT95P280X145-6N]  189.79 73.08 180 top
U35  OPA727AIDGKT  [SOP65P490X110-8N]  194.94 63.75 90 top
U36  OPA727AIDGKT  [SOP65P490X110-8N]  194.92 42.24 90 top
U37  MIC5270-4.1YM5-TR  [SOT95P280X145-5N]  201.22 50.39 180 bottom
U38  MIC5270-4.1YM5-TR  [SOT95P280X145-5N]  201.22 58.7 180 bottom
U39  MCP1702T-4002ECB  [SOT23A]  184.71 94.5 270 bottom
U40  MCP1702T-4002ECB  [SOT23A]  184.71 103.4 270 bottom
U41  AD7476AAKSZ-500RL7  [SOT95P280X145-6N]  189.79 113.69 180 top
U42  OPA727AIDGKT  [SOP65P490X110-8N]  194.94 104.37 90 top
U43  OPA727AIDGKT  [SOP65P490X110-8N]  194.92 82.85 90 top
U44  MIC5270-4.1YM5-TR  [SOT95P280X145-5N]  201.22 91.01 180 bottom
U45  MIC5270-4.1YM5-TR  [SOT95P280X145-5N]  201.22 99.31 180 bottom
U46  MCP1702T-4002ECB  [SOT23A]  184.71 135.03 270 bottom
U47  MCP1702T-4002ECB  [SOT23A]  184.71 143.94 270 bottom
U48  AD7476AAKSZ-500RL7  [SOT95P280X145-6N]  189.79 154.23 180 top
U49  OPA727AIDGKT  [SOP65P490X110-8N]  194.94 144.91 90 top
U50  OPA727AIDGKT  [SOP65P490X110-8N]  194.92 123.39 90 top
U51  MIC5270-4.1YM5-TR  [SOT95P280X145-5N]  201.22 131.55 180 bottom
U52  MIC5270-4.1YM5-TR  [SOT95P280X145-5N]  201.22 139.85 180 bottom
U53  MCP1702T-4002ECB  [SOT23A]  184.71 176.46 270 bottom
U54  MCP1702T-4002ECB  [SOT23A]  184.71 185.37 270 bottom
U55  AD7476AAKSZ-500RL7  [SOT95P280X145-6N]  189.79 195.66 180 top
U56  OPA727AIDGKT  [SOP65P490X110-8N]  194.92 164.82 90 top
U57  OPA727AIDGKT  [SOP65P490X110-8N]  194.94 186.33 90 top
U58  MIC5270-4.1YM5-TR  [SOT95P280X145-5N]  201.22 172.97 180 bottom
U59  MIC5270-4.1YM5-TR  [SOT95P280X145-5N]  201.22 181.28 180 bottom
U60  AD8531AKSZ-REEL7  [SOT_23_5]  147.52 37.23 90 bottom
U61  ADR5043BKSZ-REEL7  [SC_70_3]  148.36 25.32 0 bottom
U62  LD2980ABM33TR  [SOT_23_5]  277.34 124.64 180 bottom
U63  MCP1702T-4002ECB  [SOT23A]  238.38 68.76 90 bottom
U64  ADR5043BKSZ-REEL7  [SC_70_3]  227.58 74.6 90 top
U65  DAC8811ICDGKT  [SOP65P490X110-8N]  233.04 79.04 270 top
U66  OPA727AIDGKT  [SOP65P490X110-8N]  228.47 86.79 0 top
U67  OPA727AIDGKT  [SOP65P490X110-8N]  231.78 69.39 270 top
U68  MIC5270-4.1YM5-TR  [SOT95P280X145-5N]  220.6 76.71 0 bottom
U69  MIC5270-4.1YM5-TR  [SOT95P280X145-5N]  220.6 69.32 0 bottom
U71  MCP1702T-4002ECB  [SOT23A]  238.38 100.43 90 bottom
U72  ADR5043BKSZ-REEL7  [SC_70_3]  227.58 106.27 90 top
U73  OPA727AIDGKT  [SOP65P490X110-8N]  228.47 118.47 0 top
U74  DAC8811ICDGKT  [SOP65P490X110-8N]  233.04 110.72 270 top
U75  OPA727AIDGKT  [SOP65P490X110-8N]  231.78 101.07 270 top
U76  MIC5270-4.1YM5-TR  [SOT95P280X145-5N]  220.6 108.38 0 bottom
U77  MIC5270-4.1YM5-TR  [SOT95P280X145-5N]  220.6 100.99 0 bottom
U79  MCP1702T-4002ECB  [SOT23A]  238.38 134.7 90 bottom
U80  ADR5043BKSZ-REEL7  [SC_70_3]  227.58 140.54 90 top
U81  DAC8811ICDGKT  [SOP65P490X110-8N]  233.04 144.98 270 top
U82  OPA727AIDGKT  [SOP65P490X110-8N]  231.78 135.33 270 top
U83  OPA727AIDGKT  [SOP65P490X110-8N]  228.47 152.73 0 top
U84  MIC5270-4.1YM5-TR  [SOT95P280X145-5N]  220.6 142.65 0 bottom
U85  MIC5270-4.1YM5-TR  [SOT95P280X145-5N]  220.6 135.25 0 bottom
U87  MCP1702T-4002ECB  [SOT23A]  238.38 168.73 90 bottom
U88  ADR5043BKSZ-REEL7  [SC_70_3]  227.58 174.57 90 top
U89  OPA727AIDGKT  [SOP65P490X110-8N]  228.47 186.77 0 top
U90  DAC8811ICDGKT  [SOP65P490X110-8N]  233.04 179.02 270 top
U91  OPA727AIDGKT  [SOP65P490X110-8N]  231.78 169.37 270 top
U92  MIC5270-4.1YM5-TR  [SOT95P280X145-5N]  220.6 176.68 0 bottom
U93  MIC5270-4.1YM5-TR  [SOT95P280X145-5N]  220.6 169.29 0 bottom
U95  MCP1702T-4002ECB  [SOT23A]  270.92 68.76 90 bottom
U96  ADR5043BKSZ-REEL7  [SC_70_3]  260.12 74.6 90 top
U97  OPA727AIDGKT  [SOP65P490X110-8N]  261.01 86.79 0 top
U98  DAC8811ICDGKT  [SOP65P490X110-8N]  265.58 79.04 270 top
U99  OPA727AIDGKT  [SOP65P490X110-8N]  264.31 69.39 270 top
U100  MIC5270-4.1YM5-TR  [SOT95P280X145-5N]  253.14 76.71 0 bottom
U101  MIC5270-4.1YM5-TR  [SOT95P280X145-5N]  253.14 69.32 0 bottom
U103  MCP1702T-4002ECB  [SOT23A]  270.92 100.43 90 bottom
U104  ADR5043BKSZ-REEL7  [SC_70_3]  260.12 106.27 90 top
U105  OPA727AIDGKT  [SOP65P490X110-8N]  261.01 118.47 0 top
U106  DAC8811ICDGKT  [SOP65P490X110-8N]  265.58 110.72 270 top
U107  OPA727AIDGKT  [SOP65P490X110-8N]  264.31 101.07 270 top
U108  MIC5270-4.1YM5-TR  [SOT95P280X145-5N]  253.14 108.38 0 bottom
U109  MIC5270-4.1YM5-TR  [SOT95P280X145-5N]  253.14 100.99 0 bottom
U111  MCP1702T-4002ECB  [SOT23A]  270.92 134.7 90 bottom
U112  ADR5043BKSZ-REEL7  [SC_70_3]  260.12 140.54 90 top
U113  OPA727AIDGKT  [SOP65P490X110-8N]  261.01 152.73 0 top
U114  DAC8811ICDGKT  [SOP65P490X110-8N]  265.58 144.98 270 top
U115  OPA727AIDGKT  [SOP65P490X110-8N]  264.31 135.33 270 top
U116  MIC5270-4.1YM5-TR  [SOT95P280X145-5N]  253.14 142.65 0 bottom
U117  MIC5270-4.1YM5-TR  [SOT95P280X145-5N]  253.14 135.25 0 bottom
U119  MCP1702T-4002ECB  [SOT23A]  270.92 168.73 90 bottom
U120  ADR5043BKSZ-REEL7  [SC_70_3]  260.12 174.57 90 top
U121  OPA727AIDGKT  [SOP65P490X110-8N]  261.01 186.77 0 top
U122  DAC8811ICDGKT  [SOP65P490X110-8N]  265.58 179.02 270 top
U123  OPA727AIDGKT  [SOP65P490X110-8N]  264.31 169.37 270 top
U124  MIC5270-4.1YM5-TR  [SOT95P280X145-5N]  253.14 176.68 0 bottom
U126  NC7SZ14M5X  [SOT23_SCHMMIT]  23.9 43.89 90 top
U127  NC7SZ14M5X  [SOT23_SCHMMIT]  30.73 43.89 90 top
U128  NC7SZ14M5X  [SOT23_SCHMMIT]  37.57 43.89 90 top
U129  NC7SZ14M5X  [SOT23_SCHMMIT]  44.4 43.89 90 top
U130  NC7SZ14M5X  [SOT23_SCHMMIT]  26.11 50.55 90 top
U131  NC7SZ14M5X  [SOT23_SCHMMIT]  32.94 50.55 90 top
U132  NC7SZ14M5X  [SOT23_SCHMMIT]  39.78 50.55 90 top
U133  NC7SZ14M5X  [SOT23_SCHMMIT]  46.61 50.55 90 top
U134  NC7SZ14M5X  [SOT23_SCHMMIT]  54.23 43.89 90 top
U135  NC7SZ14M5X  [SOT23_SCHMMIT]  61.14 43.89 90 top
U136  NC7SZ14M5X  [SOT23_SCHMMIT]  68.05 43.89 90 top
U137  NC7SZ14M5X  [SOT23_SCHMMIT]  74.88 43.89 90 top
U138  NC7SZ14M5X  [SOT23_SCHMMIT]  56.21 50.55 90 top
U139  NC7SZ14M5X  [SOT23_SCHMMIT]  63.12 50.55 90 top
U140  NC7SZ14M5X  [SOT23_SCHMMIT]  70.03 50.55 90 top
U141  NC7SZ14M5X  [SOT23_SCHMMIT]  76.86 50.55 90 top
U142  NC7SZ14M5X  [SOT23_SCHMMIT]  87.63 43.94 270 top
U143  NC7SZ14M5X  [SOT23_SCHMMIT]  93.51 43.94 270 top
U144  NC7SZ14M5X  [SOT23_SCHMMIT]  99.4 43.94 270 top
U145  NC7SZ14M5X  [SOT23_SCHMMIT]  105.28 43.94 270 top
U146  NC7SZ14M5X  [SOT23_SCHMMIT]  89.51 50.6 270 top
U147  NC7SZ14M5X  [SOT23_SCHMMIT]  95.39 50.6 270 top
U148  NC7SZ14M5X  [SOT23_SCHMMIT]  101.28 50.6 270 top
U149  NC7SZ14M5X  [SOT23_SCHMMIT]  107.16 50.6 270 top
U150  NC7SZ14M5X  [SOT23_SCHMMIT]  114.47 43.94 270 top
U151  NC7SZ14M5X  [SOT23_SCHMMIT]  120.35 43.94 270 top
U152  NC7SZ14M5X  [SOT23_SCHMMIT]  126.24 43.94 270 top
U153  NC7SZ14M5X  [SOT23_SCHMMIT]  132.12 43.94 270 top
U154  NC7SZ14M5X  [SOT23_SCHMMIT]  116.33 50.6 270 top
U155  NC7SZ14M5X  [SOT23_SCHMMIT]  122.22 50.6 270 top
U156  NC7SZ14M5X  [SOT23_SCHMMIT]  128.1 50.6 270 top
U157  NC7SZ14M5X  [SOT23_SCHMMIT]  133.98 50.6 270 top
U160  SBAT54SLT1G  [SOT91P240X110-3N]  157.3 27.13 0 bottom
U161  SBAT54SLT1G  [SOT91P240X110-3N]  165.48 27.13 0 bottom
U162  SBAT54SLT1G  [SOT91P240X110-3N]  171.93 27.13 0 bottom
U163  SBAT54SLT1G  [SOT91P240X110-3N]  178.82 27.13 0 bottom
U164  SBAT54SLT1G  [SOT91P240X110-3N]  188.47 27.36 0 bottom
U165  SBAT54SLT1G  [SOT91P240X110-3N]  194.64 27.38 0 bottom
U166  SBAT54SLT1G  [SOT91P240X110-3N]  201.22 27.38 0 bottom
U167  SBAT54SLT1G  [SOT91P240X110-3N]  207.62 27.41 0 bottom
U168  NC7SZ14M5X  [SOT23_SCHMMIT]  108.94 83.1 180 top
U169  NC7SZ14M5X  [SOT23_SCHMMIT]  118.11 113.18 180 top
U170  NC7SZ14M5X  [SOT23_SCHMMIT]  108.94 138.05 180 top
U171  NC7SZ14M5X  [SOT23_SCHMMIT]  108.94 172.4 180 top
U172  NC7SZ14M5X  [SOT23_SCHMMIT]  118.11 84.45 180 top
U173  NC7SZ14M5X  [SOT23_SCHMMIT]  108.94 110.54 180 top
U174  NC7SZ14M5X  [SOT23_SCHMMIT]  118.11 140.77 180 top
U175  NC7SZ14M5X  [SOT23_SCHMMIT]  118.11 168.94 180 top
U176  NC7SZ14M5X  [SOT23_SCHMMIT]  117.78 97.74 0 top
U177  NC7SZ14M5X  [SOT23_SCHMMIT]  118.11 126.12 0 top
U178  NC7SZ14M5X  [SOT23_SCHMMIT]  118.11 154.28 0 top
U179  NC7SZ14M5X  [SOT23_SCHMMIT]  118.11 182.45 0 top
U180  NC7SZ14M5X  [SOT23_SCHMMIT]  108.94 103.14 0 top
U181  NC7SZ14M5X  [SOT23_SCHMMIT]  108.94 130.61 0 top
U182  NC7SZ14M5X  [SOT23_SCHMMIT]  108.94 158.09 0 top
U183  NC7SZ14M5X  [SOT23_SCHMMIT]  108.94 185.57 0 top
U184  SBAT54SLT1G  [SOT91P240X110-3N]  24.05 49.99 270 bottom
U185  SBAT54SLT1G  [SOT91P240X110-3N]  30.95 49.99 270 bottom
U186  SBAT54SLT1G  [SOT91P240X110-3N]  37.85 49.99 270 bottom
U187  SBAT54SLT1G  [SOT91P240X110-3N]  44.75 49.99 270 bottom
U188  SBAT54SLT1G  [SOT91P240X110-3N]  27.41 53.64 270 bottom
U189  SBAT54SLT1G  [SOT91P240X110-3N]  34.31 53.64 270 bottom
U190  SBAT54SLT1G  [SOT91P240X110-3N]  41.21 53.64 270 bottom
U191  SBAT54SLT1G  [SOT91P240X110-3N]  48.11 53.64 270 bottom
U192  SBAT54SLT1G  [SOT91P240X110-3N]  54.23 49.99 270 bottom
U193  SBAT54SLT1G  [SOT91P240X110-3N]  61.13 49.99 270 bottom
U194  SBAT54SLT1G  [SOT91P240X110-3N]  68.03 49.99 270 bottom
U195  SBAT54SLT1G  [SOT91P240X110-3N]  74.93 49.99 270 bottom
U196  SBAT54SLT1G  [SOT91P240X110-3N]  58.09 53.64 270 bottom
U197  SBAT54SLT1G  [SOT91P240X110-3N]  64.99 53.64 270 bottom
U198  SBAT54SLT1G  [SOT91P240X110-3N]  71.89 53.64 270 bottom
U199  SBAT54SLT1G  [SOT91P240X110-3N]  78.79 53.64 270 bottom
U200  NC7SZ14M5X  [SOT23_SCHMMIT]  118.11 76.83 0 top
U201  NC7SZ14M5X  [SOT23_SCHMMIT]  108.94 89.4 0 top
U202  NC7SZ14M5X  [SOT23_SCHMMIT]  118.11 104.88 0 top
U203  NC7SZ14M5X  [SOT23_SCHMMIT]  108.94 116.88 0 top
U204  NC7SZ14M5X  [SOT23_SCHMMIT]  118.11 133.16 0 top
U205  NC7SZ14M5X  [SOT23_SCHMMIT]  108.94 144.35 0 top
U206  NC7SZ14M5X  [SOT23_SCHMMIT]  103.12 164.96 0 top
U207  NC7SZ14M5X  [SOT23_SCHMMIT]  118.11 175.41 0 top
U208  NC7SZ14M5X  [SOT23_SCHMMIT]  108.94 96.27 0 top
U209  NC7SZ14M5X  [SOT23_SCHMMIT]  118.11 90.92 0 top
U210  NC7SZ14M5X  [SOT23_SCHMMIT]  108.94 123.74 0 top
U211  NC7SZ14M5X  [SOT23_SCHMMIT]  118.11 119.08 0 top
U212  NC7SZ14M5X  [SOT23_SCHMMIT]  108.94 151.22 0 top
U213  NC7SZ14M5X  [SOT23_SCHMMIT]  118.11 147.24 0 top
U214  NC7SZ14M5X  [SOT23_SCHMMIT]  108.94 178.7 0 top
U215  NC7SZ14M5X  [SOT23_SCHMMIT]  118.11 161.33 0 top
U300  -  [FPGA]  56.31 130.02 180 top
U301  JCA1005D01  [DIP_24]  48.95 179.63 90 top
U302  JCA0205S03  [DIP_24]  48.95 154.25 90 top
U303  CON_POT  [CONECTOR_POTENCIA_SMD]  16.61 160.17 90 top

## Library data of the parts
C1 C2 C4 C5 C7-C93 C96-C102 C105-C111 C114-C120 C123-C129 C132-C138 C141-C147 C150-C244 = C
D17-D32 D65-D96 = DIODE_0
J1 J3 J5 J7 J9 J10 J13 J14 = CON12: User Part Number: ***
J15 J16 = CON12_0: User Part Number: ***
J17 J18 = CON2: User Part Number: ***
R1-R214 R223 = R
U1 U2 U5 U11 U12 U18 U19 U25 U26 U32 U33 U39 U40 U46 U47 U53 U54 U63 U71 U79 U87 U95 U103 U111 U119 = MCP1702T-4002ECB
U3 = OPA365AMDBVTEP
U4 = LM4040AEX3-3_3T
U6 U13 U20 U27 U34 U41 U48 U55 = AD7476AAKSZ-500RL7
U7 U8 U14 U15 U21 U22 U28 U29 U35 U36 U42 U43 U49 U50 U56 U57 U66 U67 U73 U75 U82 U83 U89 U91 U97 U99 U105 U107 U113 U115 U121 U123 = OPA727AIDGKT
U9 U10 U16 U17 U23 U24 U30 U31 U37 U38 U44 U45 U51 U52 U58 U59 U68 U69 U76 U77 U84 U85 U92 U93 U100 U101 U108 U109 U116 U117 U124 = MIC5270-4.1YM5-TR
U60 = AD8531AKSZ-REEL7_0
U61 U64 U72 U80 U88 U96 U104 U112 U120 = ADR5043BKSZ-REEL7
U62 = LDO_3V3
U65 U74 U81 U90 U98 U106 U114 U122 = DAC8811ICDGKT
U126-U157 U168-U183 U200-U215 = NC7SZ14M5X
U160-U167 U184-U199 = BZX84C4V3
U300 = FPGA
U301 = FUENTE_+-5V
U302 = FUENTE_3V3
U303 = conector_potencia_smd_0

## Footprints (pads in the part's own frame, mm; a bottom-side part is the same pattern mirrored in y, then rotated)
0805
  rect 1.3x1.5 smd: 1(-0.95,0) 2(0.95,0)
1206
  custom 0.273x0.273 smd: 1(-1.465,0)
  custom 0.235x0.235 smd: 2(1.54,0)
CONECTOR_POTENCIA_SMD
  rect 3x2 smd: 1_1(-5.5,0.5) 1_2(-5.5,-5.5) 2(5.5,-5.5) 3(5.5,0.5)
DIP_24
  rect 1.676x1.676 hole 1.118: 1(-7.24,13.94)
  round 1.676 hole 1.118: 2(-7.24,11.4) 3(-7.24,8.86) 4(-7.24,6.32) 5(-7.24,3.78) 6(-7.24,1.24) 7(-7.24,-1.3) 8(-7.24,-3.84) 9(-7.24,-6.38) 10(-7.24,-8.92) 11(-7.24,-11.46) 12(-7.24,-14) 13(8,-14) 14(8,-11.46) 15(8,-8.92) 16(8,-6.38) 17(8,-3.84) 18(8,-1.3) 19(8,1.24) 20(8,3.78) 21(8,6.32) 22(8,8.86) 23(8,11.4) 24(8,13.94)
FPGA
  rect 0.27x1 smd: 1(19.5,32) 2(19,32) 3(18.5,32) 4(18,32) 5(17.5,32) 6(17,32) 7(16.5,32) 8(16,32) 9(15.5,32) 10(15,32) 11(14.5,32) 12(14,32) 13(13.5,32) 14(13,32) 15(12.5,32) 16(12,32) 17(11.5,32) 18(11,32) 19(10.5,32) 20(10,32) 21(9.5,32) 22(9,32) 23(8.5,32) 24(8,32) 25(7.5,32) 26(7,32) 27(6.5,32) 28(6,32) 29(5.5,32) 30(5,32) 31(4.5,32) 32(4,32) 33(3.5,32) 34(3,32) 35(2.5,32) 36(2,32) 37(1.5,32) 38(1,32) 39(0.5,32) 40(0,32) 41(0,37.25) 42(0.5,37.25) 43(1,37.25) 44(1.5,37.25) 45(2,37.25) 46(2.5,37.25) 47(3,37.25) 48(3.5,37.25) 49(4,37.25) 50(4.5,37.25) 51(5,37.25) 52(5.5,37.25) 53(6,37.25) 54(6.5,37.25) 55(7,37.25) 56(7.5,37.25) 57(8,37.25) 58(8.5,37.25) 59(9,37.25) 60(9.5,37.25) 61(10,37.25) 62(10.5,37.25) 63(11,37.25) 64(11.5,37.25) 65(12,37.25) 66(12.5,37.25) 67(13,37.25) 68(13.5,37.25) 69(14,37.25) 70(14.5,37.25) 71(15,37.25) 72(15.5,37.25) 73(16,37.25) 74(16.5,37.25) 75(17,37.25) 76(17.5,37.25) 77(18,37.25) 78(18.5,37.25) 79(19,37.25) 80(19.5,37.25) 81(19.5,0) 82(19,0) 83(18.5,0) 84(18,0) 85(17.5,0) 86(17,0) 87(16.5,0) 88(16,0) 89(15.5,0) 90(15,0) 91(14.5,0) 92(14,0) 93(13.5,0) 94(13,0) 95(12.5,0) 96(12,0) 97(11.5,0) 98(11,0) 99(10.5,0) 100(10,0) 101(9.5,0) 102(9,0) 103(8.5,0) 104(8,0) 105(7.5,0) 106(7,0) 107(6.5,0) 108(6,0) 109(5.5,0) 110(5,0) 111(4.5,0) 112(4,0) 113(3.5,0) 114(3,0) 115(2.5,0) 116(2,0) 117(1.5,0) 118(1,0) 119(0.5,0) 120(0,0) 121(0,5.25) 122(0.5,5.25) 123(1,5.25) 124(1.5,5.25) 125(2,5.25) 126(2.5,5.25) 127(3,5.25) 128(3.5,5.25) 129(4,5.25) 130(4.5,5.25) 131(5,5.25) 132(5.5,5.25) 133(6,5.25) 134(6.5,5.25) 135(7,5.25) 136(7.5,5.25) 137(8,5.25) 138(8.5,5.25) 139(9,5.25) 140(9.5,5.25) 141(10,5.25) 142(10.5,5.25) 143(11,5.25) 144(11.5,5.25) 145(12,5.25) 146(12.5,5.25) 147(13,5.25) 148(13.5,5.25) 149(14,5.25) 150(14.5,5.25) 151(15,5.25) 152(15.5,5.25) 153(16,5.25) 154(16.5,5.25) 155(17,5.25) 156(17.5,5.25) 157(18,5.25) 158(18.5,5.25) 159(19,5.25) 160(19.5,5.25)
  rect 1.4x2.11 smd: 161(-2.2,2.4) 162(21.7,2.4) 163(-2.2,34.4) 164(21.7,34.4)
JUMPER2
  round 1.524 hole 0.914: 1(0,0) 2(2.54,0)
JUMPER12
  round 1.524 hole 0.914: 1(0,0) 2(2.54,0) 3(5.08,0) 4(7.62,0) 5(10.16,0) 6(12.7,0) 7(0,2.54) 8(2.54,2.54) 9(5.08,2.54) 10(7.62,2.54) 11(10.16,2.54) 12(12.7,2.54)
JUMPER12_F
  round 1.524 hole 0.914: 1(0,0) 2(0,2.54) 3(2.54,0) 4(2.54,2.54) 5(5.08,0) 6(5.08,2.54) 7(7.62,0) 8(7.62,2.54) 9(10.16,0) 10(10.16,2.54) 11(12.7,0) 12(12.7,2.54)
JUMPER12X1
  round 1.524 hole 0.914: 1(0,0) 2(2.54,0) 3(5.08,0) 4(7.62,0) 5(10.16,0) 6(12.7,0) 7(15.24,0) 8(17.78,0) 9(20.32,0) 10(22.86,0) 11(25.4,0) 12(27.94,0)
SC_70_3
  rect 0.457x1.118 smd: 1(-0.65,-0.991) 2(0.65,-0.991) 3(0,0.991)
SOD123
  custom 0.27x0.27 smd: A(1.6,0) C(-1.645,0)
SOP65P490X110-8N
  rect 1.422x0.432 smd: 1(-2.184,0.965) 2(-2.184,0.33) 3(-2.184,-0.33) 4(-2.184,-0.965) 5(2.184,-0.965) 6(2.184,-0.33) 7(2.184,0.33) 8(2.184,0.965)
SOT23_SCHMMIT
  rect 1.27x0.559 smd: 1(-1.295,0.94) 2(-1.295,0) 3(-1.295,-0.94) 4(1.295,-0.94) 5(1.295,0.94)
SOT23A
  rect 0.559x1.321 smd: 1(-0.94,-1.194) 2(0.94,-1.194) 3(0,1.194)
SOT91P240X110-3N
  rect 1.321x0.559 smd: 1(-1.016,0.914) 2(-1.016,-0.914) 3(1.016,0)
SOT95P280X145-5N
  rect 1.27x0.559 smd: 1(-1.295,0.94) 2(-1.295,0) 3(-1.295,-0.94) 4(1.295,-0.94) 5(1.295,0.94)
SOT95P280X145-6N
  rect 1.27x0.559 smd: 1(-1.295,0.94) 2(-1.295,0) 3(-1.295,-0.94) 4(1.295,-0.94) 5(1.295,0) 6(1.295,0.94)
SOT_23_5
  rect 1.27x0.559 smd: 1(-1.295,0.94) 2(-1.295,0) 3(-1.295,-0.94) 4(1.295,-0.94) 5(1.295,0.94)

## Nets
1.2V: U300.73(1.2V#73) U300.74(1.2V#74) U300.153(1.2V#153) U300.154(1.2V#154)
2.5V: U300.53(2.5V#53) U300.54(2.5V#54) U300.133(2.5V#133) U300.134(2.5V#134)
3.3V: U300.33(3.3V#33) U300.34(3.3V#34) U300.115(3.3V#115) U300.116(3.3V#116)
3V3: C181.1 C182.1 C183.1 C184.1 C185.1 C186.1 C187.1 C188.1 C189.1 C190.1 C191.1 C192.1 C193.1 C194.1 C195.1 C196.1 C197.1 C198.1 C199.1 C200.1 C201.1 C202.1 C203.1 C204.1 C205.1 C206.1 C207.1 C208.1 C209.1 C210.1 C211.1 C212.1 C213.1 C214.1 C215.1 C216.1 C217.1 C218.1 C219.1 C220.1 C221.1 C222.1 C223.1 C224.1 C225.1 C226.1 C227.1 C228.1 C229.1 C230.1 C231.1 C232.1 C233.1 C234.1 C235.1 C236.1 C237.1 C238.1 C239.1 C240.1 C241.1 C242.1 C243.1 C244.1 D65.C D67.C D69.C D71.C D73.C D75.C D77.C D79.C D81.C D83.C D85.C D87.C D89.C D91.C D93.C D95.C J1.6 J1.7 J5.6 J5.7 J9.6 J9.7 J13.6 J13.7 R167.2 R170.2 R173.2 R176.2 R179.2 R182.2 R185.2 R188.2 R191.2 R194.2 R197.2 R200.2 R203.2 R206.2 R209.2 R212.2 U126.5(VCC) U127.5(VCC) U128.5(VCC) U129.5(VCC) U130.5(VCC) U131.5(VCC) U132.5(VCC) U133.5(VCC) U134.5(VCC) U135.5(VCC) U136.5(VCC) U137.5(VCC) U138.5(VCC) U139.5(VCC) U140.5(VCC) U141.5(VCC) U142.5(VCC) U143.5(VCC) U144.5(VCC) U145.5(VCC) U146.5(VCC) U147.5(VCC) U148.5(VCC) U149.5(VCC) U150.5(VCC) U151.5(VCC) U152.5(VCC) U153.5(VCC) U154.5(VCC) U155.5(VCC) U156.5(VCC) U157.5(VCC) U168.5(VCC) U169.5(VCC) U170.5(VCC) U171.5(VCC) U172.5(VCC) U173.5(VCC) U174.5(VCC) U175.5(VCC) U176.5(VCC) U177.5(VCC) U178.5(VCC) U179.5(VCC) U180.5(VCC) U181.5(VCC) U182.5(VCC) U183.5(VCC) U184.2(C) U185.2(C) U186.2(C) U187.2(C) U188.2(C) U189.2(C) U190.2(C) U191.2(C) U192.2(C) U193.2(C) U194.2(C) U195.2(C) U196.2(C) U197.2(C) U198.2(C) U199.2(C) U200.5(VCC) U201.5(VCC) U202.5(VCC) U203.5(VCC) U204.5(VCC) U205.5(VCC) U206.5(VCC) U207.5(VCC) U208.5(VCC) U209.5(VCC) U210.5(VCC) U211.5(VCC) U212.5(VCC) U213.5(VCC) U214.5(VCC) U215.5(VCC) U302.14(+VOUT)
3V3ADC: C173.2 C174.2 C175.2 C176.2 C177.2 C178.2 C179.2 C180.2 R223.2 U6.1(VDD) U13.1(VDD) U20.1(VDD) U27.1(VDD) U34.1(VDD) U41.1(VDD) U48.1(VDD) U55.1(VDD)
3V3DAC: C86.2 U62.5(VOUT) U65.7(VDD) U74.7(VDD) U81.7(VDD) U90.7(VDD) U98.7(VDD) U106.7(VDD) U114.7(VDD) U122.7(VDD)
3VPROT: D17.C D19.C D21.C D23.C D25.C D27.C D29.C D31.C R76.1 U60.1(VOUTA) U160.2(C) U161.2(C) U162.2(C) U163.2(C) U164.2(C) U165.2(C) U166.2(C) U167.2(C)
5V: U300.85(5V)
5VU: J3.2 J3.11 J7.2 J7.11 J10.2 J10.11 J14.2 J14.11 U300.81(5VB2B#81) U300.82(5VB2B#82) U300.83(5VB2B#83) U300.84(5VB2B#84) U301.22(+VIN#22) U301.23(+VIN#23) U302.22(+VIN#22) U302.23(+VIN#23) U303.1_1(VCC#1_1) U303.1_2(VCC#1_2)
+5V: C1.2 C4.2 C8.2 C15.2 C18.2 C25.2 C28.2 C35.2 C38.2 C45.2 C48.2 C55.2 C58.2 C65.2 C68.2 C75.2 C78.2 C85.2 C88.2 C96.2 C105.2 C114.2 C123.2 C132.2 C141.2 C150.2 R1.1 R77.2 U1.3(VIN) U2.3(VIN) U5.3(VIN) U11.3(VIN) U12.3(VIN) U18.3(VIN) U19.3(VIN) U25.3(VIN) U26.3(VIN) U32.3(VIN) U33.3(VIN) U39.3(VIN) U40.3(VIN) U46.3(VIN) U47.3(VIN) U53.3(VIN) U54.3(VIN) U60.5(+V) U62.1(VIN) U62.3(INHIBIT) U63.3(VIN) U71.3(VIN) U79.3(VIN) U87.3(VIN) U95.3(VIN) U103.3(VIN) U111.3(VIN) U119.3(VIN) U301.14(+VOUT)
-5V: C11.2 C13.2 C22.2 C23.2 C32.2 C33.2 C42.2 C43.2 C52.2 C53.2 C62.2 C63.2 C72.2 C73.2 C82.2 C83.2 C90.2 C92.2 C99.2 C101.2 C108.2 C110.2 C117.2 C119.2 C126.2 C128.2 C135.2 C137.2 C144.2 C146.2 C153.2 C155.2 R80.2 R85.2 R90.2 R95.2 R100.2 R105.2 R110.2 R115.2 U9.5(-IN) U10.5(-IN) U16.5(-IN) U17.5(-IN) U23.5(-IN) U24.5(-IN) U30.5(-IN) U31.5(-IN) U37.5(-IN) U38.5(-IN) U44.5(-IN) U45.5(-IN) U51.5(-IN) U52.5(-IN) U58.5(-IN) U59.5(-IN) U68.5(-IN) U69.5(-IN) U76.5(-IN) U77.5(-IN) U84.5(-IN) U85.5(-IN) U92.5(-IN) U93.5(-IN) U100.5(-IN) U101.5(-IN) U108.5(-IN) U109.5(-IN) U116.5(-IN) U117.5(-IN) U124.5(-IN) U301.11(-VOUT)
VCCCIO0: U300.1(VCCCIO0#1) U300.2(VCCCIO0#2) U300.4(VCCCIO0#4)
/CS_I: J15.9 U200.2(A) U202.2(A) U204.2(A) U206.2(A) U300.132(V2_IO_12_N)
/CS_I_1: U6.6(CS*) U34.6(CS*) U200.4(Y)
/CS_I_2: U13.6(CS*) U41.6(CS*) U202.4(Y)
/CS_I_3: U20.6(CS*) U48.6(CS*) U204.4(Y)
/CS_I_4: U27.6(CS*) U55.6(CS*) U206.4(Y)
/CS_O: J16.7 U209.2(A) U211.2(A) U213.2(A) U215.2(A) U300.108(V0_IO_22)
/CS_O_1: U65.8(~CS) U98.8(~CS) U209.4(Y)
/CS_O_2: U74.8(~CS) U106.8(~CS) U211.4(Y)
/CS_O_3: U81.8(~CS) U114.8(~CS) U213.4(Y)
/CS_O_4: U90.8(~CS) U122.8(~CS) U215.4(Y)
A_GND: C1.1 C2.1 C4.1 C5.1 C7.1 C8.1 C10.1 C11.1 C12.1 C13.1 C14.1 C15.1 C16.1 C17.1 C18.1 C20.1 C21.1 C22.1 C23.1 C24.1 C25.1 C26.1 C27.1 C28.1 C30.1 C31.1 C32.1 C33.1 C34.1 C35.1 C36.1 C37.1 C38.1 C40.1 C41.1 C42.1 C43.1 C44.1 C45.1 C46.1 C47.1 C48.1 C50.1 C51.1 C52.1 C53.1 C54.1 C55.1 C56.1 C57.1 C58.1 C60.1 C61.1 C62.1 C63.1 C64.1 C65.1 C66.1 C67.1 C68.1 C70.1 C71.1 C72.1 C73.1 C74.1 C75.1 C76.1 C77.1 C78.1 C80.1 C81.1 C82.1 C83.1 C84.1 C85.1 C86.1 C87.1 C88.1 C90.1 C91.1 C92.1 C93.1 C96.1 C97.1 C99.1 C100.1 C101.1 C102.1 C105.1 C106.1 C108.1 C109.1 C110.1 C111.1 C114.1 C115.1 C117.1 C118.1 C119.1 C120.1 C123.1 C124.1 C126.1 C127.1 C128.1 C129.1 C132.1 C133.1 C135.1 C136.1 C137.1 C138.1 C141.1 C142.1 C144.1 C145.1 C146.1 C147.1 C150.1 C151.1 C153.1 C154.1 C155.1 C156.1 C157.2 C158.2 C159.2 C160.2 C161.2 C162.2 C163.2 C164.2 C165.2 C166.2 C167.2 C168.2 C169.2 C170.2 C171.2 C172.2 C173.1 C174.1 C175.1 C176.1 C177.1 C178.1 C179.1 C180.1 C181.2 C182.2 C183.2 C184.2 C185.2 C186.2 C187.2 C188.2 C189.2 C190.2 C191.2 C192.2 C193.2 C194.2 C195.2 C196.2 C197.2 C198.2 C199.2 C200.2 C201.2 C202.2 C203.2 C204.2 C205.2 C206.2 C207.2 C208.2 C209.2 C210.2 C211.2 C212.2 C213.2 C214.2 C215.2 C216.2 C217.2 C218.2 C219.2 C220.2 C221.2 C222.2 C223.2 C224.2 C225.2 C226.2 C227.2 C228.2 C229.2 C230.2 C231.2 C232.2 C233.2 C234.2 C235.2 C236.2 C237.2 C238.2 C239.2 C240.2 C241.2 C242.2 C243.2 C244.2 D18.A D20.A D22.A D24.A D26.A D28.A D30.A D32.A D66.A D68.A D70.A D72.A D74.A D76.A D78.A D80.A D82.A D84.A D86.A D88.A D90.A D92.A D94.A D96.A J1.1 J1.12 J3.1 J3.3 J3.5 J3.8 J3.10 J3.12 J5.1 J5.12 J7.1 J7.3 J7.5 J7.8 J7.10 J7.12 J9.1 J9.12 J10.1 J10.3 J10.5 J10.8 J10.10 J10.12 J13.1 J13.12 J14.1 J14.3 J14.5 J14.8 J14.10 J14.12 J15.11 J15.12 J16.11 J16.12 J17.1 J17.2 J18.1 J18.2 R12.2 R21.2 R30.2 R39.2 R48.2 R57.2 R66.2 R75.2 R121.2 R124.2 R127.2 R130.2 R133.2 R136.2 R139.2 R142.2 R145.2 R148.2 R151.2 R154.2 R157.2 R160.2 R163.2 R166.2 U1.1(GND) U2.1(GND) U3.2(V-) U4.2(-) U4.3(NC) U5.1(GND) U6.2(GND) U9.2(GND) U10.2(GND) U11.1(GND) U12.1(GND) U13.2(GND) U16.2(GND) U17.2(GND) U18.1(GND) U19.1(GND) U20.2(GND) U23.2(GND) U24.2(GND) U25.1(GND) U26.1(GND) U27.2(GND) U30.2(GND) U31.2(GND) U32.1(GND) U33.1(GND) U34.2(GND) U37.2(GND) U38.2(GND) U39.1(GND) U40.1(GND) U41.2(GND) U44.2(GND) U45.2(GND) U46.1(GND) U47.1(GND) U48.2(GND) U51.2(GND) U52.2(GND) U53.1(GND) U54.1(GND) U55.2(GND) U58.2(GND) U59.2(GND) U60.2(-V) U61.2(V-) U61.3(NC) U62.2(GND) U63.1(GND) U64.1(V+) U64.3(NC) U65.6(GND) U66.7(V+) U67.3(+IN) U68.2(GND) U69.2(GND) U71.1(GND) U72.1(V+) U72.3(NC) U73.7(V+) U74.6(GND) U75.3(+IN) U76.2(GND) U77.2(GND) U79.1(GND) U80.1(V+) U80.3(NC) U81.6(GND) U82.3(+IN) U83.7(V+) U84.2(GND) U85.2(GND) U87.1(GND) U88.1(V+) U88.3(NC) U89.7(V+) U90.6(GND) U91.3(+IN) U92.2(GND) U93.2(GND) U95.1(GND) U96.1(V+) U96.3(NC) U97.7(V+) U98.6(GND) U99.3(+IN) U100.2(GND) U101.2(GND) U103.1(GND) U104.1(V+) U104.3(NC) U105.7(V+) U106.6(GND) U107.3(+IN) U108.2(GND) U109.2(GND) U111.1(GND) U112.1(V+) U112.3(NC) U113.7(V+) U114.6(GND) U115.3(+IN) U116.2(GND) U117.2(GND) U119.1(GND) U120.1(V+) U120.3(NC) U121.7(V+) U122.6(GND) U123.3(+IN) U124.2(GND) U126.3(GND) U127.3(GND) U128.3(GND) U129.3(GND) U130.3(GND) U131.3(GND) U132.3(GND) U133.3(GND) U134.3(GND) U135.3(GND) U136.3(GND) U137.3(GND) U138.3(GND) U139.3(GND) U140.3(GND) U141.3(GND) U142.3(GND) U143.3(GND) U144.3(GND) U145.3(GND) U146.3(GND) U147.3(GND) U148.3(GND) U149.3(GND) U150.3(GND) U151.3(GND) U152.3(GND) U153.3(GND) U154.3(GND) U155.3(GND) U156.3(GND) U157.3(GND) U160.1(A) U161.1(A) U162.1(A) U163.1(A) U164.1(A) U165.1(A) U166.1(A) U167.1(A) U168.3(GND) U169.3(GND) U170.3(GND) U171.3(GND) U172.3(GND) U173.3(GND) U174.3(GND) U175.3(GND) U176.3(GND) U177.3(GND) U178.3(GND) U179.3(GND) U180.3(GND) U181.3(GND) U182.3(GND) U183.3(GND) U184.1(A) U185.1(A) U186.1(A) U187.1(A) U188.1(A) U189.1(A) U190.1(A) U191.1(A) U192.1(A) U193.1(A) U194.1(A) U195.1(A) U196.1(A) U197.1(A) U198.1(A) U199.1(A) U200.3(GND) U201.3(GND) U202.3(GND) U203.3(GND) U204.3(GND) U205.3(GND) U206.3(GND) U207.3(GND) U208.3(GND) U209.3(GND) U210.3(GND) U211.3(GND) U212.3(GND) U213.3(GND) U214.3(GND) U215.3(GND) U300.13(GND#13) U300.14(GND#14) U300.23(GND#23) U300.24(GND#24) U300.43(GND#43) U300.46(GND#46) U300.63(GND#63) U300.64(GND#64) U300.79(GND#79) U300.80(GND#80) U300.91(GND#91) U300.92(GND#92) U300.103(GND#103) U300.104(GND#104) U300.123(GND#123) U300.124(GND#124) U300.143(GND#143) U300.144(GND#144) U300.159(GND#159) U300.160(GND#160) U301.2(-VIN#2) U301.3(-VIN#3) U301.9(COMMON#9) U301.16(COMMON#16) U302.2(-VIN#2) U302.3(-VIN#3) U303.2(GND#2) U303.3(GND#3)
AI_1: J15.1 R4.2 U300.142(V2_IO_13_N)
AI_2: J15.4 R13.2 U300.139(V2_IO_06_P)
AI_3: J15.5 R22.2 U300.138(V2_CLK_02_P)
AI_4: J15.8 R31.2 U300.135(V2_IO_05_N)
AI_5: J15.2 R40.2 U300.141(V2_IO_06_N)
AI_6: J15.3 R49.2 U300.140(V2_IO_13_P)
AI_7: J15.6 R58.2 U300.137(V2_IO_05_P)
AI_8: J15.7 R67.2 U300.136(V2_CLK_02_N)
AO_1: J16.1 U176.2(A) U300.114(V0_IO_25)
AO_2: J16.3 U177.2(A) U300.112(V0_IO_24)
AO_3: J16.5 U178.2(A) U300.110(V0_IO_23)
AO_4: J16.9 U179.2(A) U300.106(V0_IO_21)
AO_5: J16.2 U180.2(A) U300.113(V3_IO_27)
AO_6: J16.4 U181.2(A) U300.111(V0_IO_02_N_J5)
AO_7: J16.6 U182.2(A) U300.109(V0_IO_02_P_J5)
AO_8: J16.10 U183.2(A) U300.105(V0_IO_01_N_J5)
B2B_D_P: U300.87(B2B_D_P#87) U300.89(B2B_D_P#89)
CLK_I: J15.10 U201.2(A) U203.2(A) U205.2(A) U207.2(A) U300.131(V2_IO_04_N)
CLK_I_1: U6.4(SCLK) U34.4(SCLK) U201.4(Y)
CLK_I_2: U13.4(SCLK) U41.4(SCLK) U203.4(Y)
CLK_I_3: U20.4(SCLK) U48.4(SCLK) U205.4(Y)
CLK_I_4: U27.4(SCLK) U55.4(SCLK) U207.4(Y)
CLK_O: J16.8 U208.2(A) U210.2(A) U212.2(A) U214.2(A) U300.107(V0_IO_01_P_J5)
CLK_O_1: U65.1(CLK) U98.1(CLK) U208.4(Y)
CLK_O_2: U74.1(CLK) U106.1(CLK) U210.4(Y)
CLK_O_3: U81.1(CLK) U114.1(CLK) U212.4(Y)
CLK_O_4: U90.1(CLK) U122.1(CLK) U214.4(Y)
D_GND_SIGNAL: U302.16(-VOUT)
DI_01: R131.2 U300.11(V3_IO_04)
DI_02: R134.2 U300.9(V3_IO_03)
DI_03: R137.2 U300.7(V3_IO_02)
DI_04: R141.2 U300.5(V3_IO_01)
DI_05: R120.2 U300.12(V3_IO_09)
DI_06: R123.2 U300.10(V3_IO_08)
DI_07: R126.2 U300.8(V3_IO_07)
DI_08: R129.2 U300.6(V3_IO_06)
DI_9: R156.2 U300.67(V0_IO_08_P)
DI_10: R159.2 U300.65(V0_IO_08_N)
DI_11: R162.2 U300.61(V0_IO_07_N)
DI_12: R165.2 U300.59(V0_IO_07_P)
DI_13: R144.2 U300.68(V0_IO_18_N)
DI_14: R147.2 U300.66(V0_IO_18_P)
DI_15: R150.2 U300.62(V0_IO_17_N)
DI_16: R153.2 U300.60(V0_IO_17_P)
DO_1: R179.1 U146.2(A) U300.49(V0_IO_05_P)
DO_2: R182.1 U147.2(A) U300.47(V0_CLK_02_N)
DO_3: R185.1 U148.2(A) U300.44(V0_CLK_01_P)
DO_4: R188.1 U149.2(A) U300.41(V0_CLK_03_N)
DO_5: R167.1 U142.2(A) U300.50(V0_IO_15_P)
DO_6: R170.1 U143.2(A) U300.48(V0_IO_15_N)
DO_7: R173.1 U144.2(A) U300.45(V0_CLK_02_P)
DO_8: R176.1 U145.2(A) U300.42(V0_CLK_01_N)
DO_09: R191.1 U150.2(A) U300.40(V0_CLK_04_P)
DO_10: R194.1 U151.2(A) U300.38(V0_CLK_04_N)
DO_11: R197.1 U152.2(A) U300.36(V3_IO_10)
DO_12: R200.1 U153.2(A) U300.32(V0_IO_14_P)
DO_13: R203.1 U154.2(A) U300.39(V0_CLK_03_P)
DO_14: R206.1 U155.2(A) U300.37(V0_IO_04_P)
DO_15: R209.1 U156.2(A) U300.35(V0_IO_04_N)
DO_16: R212.1 U157.2(A) U300.31(V0_IO_03_N)
N151383_AI_5_8: C50.2 R41.1 U35.3(+IN)
N151383_AO_5_8: C134.1 R106.1 U106.3(RFB) U107.6(OUT)
PHIDI_01: J1.8 R132.1
PHIDI_02: J1.9 R135.1
PHIDI_03: J1.10 R138.1
